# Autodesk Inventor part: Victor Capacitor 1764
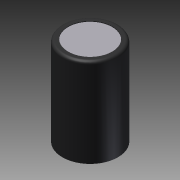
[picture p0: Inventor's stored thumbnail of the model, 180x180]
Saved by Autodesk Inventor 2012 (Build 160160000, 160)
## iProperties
Shininess: 64.0
Length Units: 11272
Angle Units: 11279
Time Units: 11290
Mass Units: 11286
Length Display Precision: 3
Angle Display Precision: 2
Compacted: True
Part Number: Victor Capacitor 1764
Document SubType Name: Modeling
Created: 2007-01
Designer: uidk0133
Density: 1 g/cm^3
Material: Default
Density: 0.0
Volumn: 0.0
Area: 0.0
PropertySet Name: Model Information
Control State: 0
Master: False
Checked Out: False
Author: uidk0133
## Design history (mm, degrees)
sketch "Sketch1"
  geometry: C1 r 6.35 at (0, 0)
  constraints: 1 centre point
  dimensions: "d0" = 12.7 diameter of C1
extrude "Extrusion1" new body sketch "Sketch1" stored distance "d1" = 20.32; taper "d2" = 0 deg
fillet "Fillet1" dims "d3" = 0.635
sketch "Sketch2"
  geometry: C1 r 5.715 at (0, 0) reference; C2 r 5.035 at (0, 0)
  constraints: 1 centre point, 1 coincident, 1 concentric
extrude "Extrusion2" cut sketch "Sketch2" distance "d4" = 0.127; taper "d5" = 0 deg
body "Solid1"
